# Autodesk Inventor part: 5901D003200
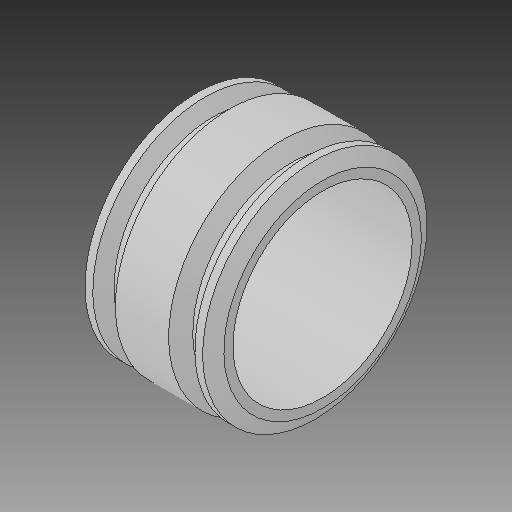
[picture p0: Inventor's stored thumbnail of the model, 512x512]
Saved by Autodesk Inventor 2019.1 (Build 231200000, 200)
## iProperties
Created: 2017-06
Part Number: 5901D003200
Material: Generic
Description: PLASSON COUPLER 20''DIPS
Document SubType Name: Modeling
Designer: KIM
Mass: 96874 g
Surface Area: 34549.7 cm^2
Volume: 96874 cm^3
Density: 1 g/cm^3
Appearance: Default
Author: KIM
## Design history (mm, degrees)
derived "5901D.ipt"
feature "Solid1::5901D.ipt"
tag "TaggingFeature1"
body "Solid1"
other parameters: "d13" = 375.92, "d15" = 187.96, "d16" = 187.96, "d17" = 505.7, "d22" = 632.968, "d23" = 643.382, "d24" = 557.01184, "d25" = 150 deg, "d26" = 150.368, "d27" = 120 deg, "d29" = 316.484, "d35" = 15, "d39" = 0, "d40" = 4, "d41" = 14, "d42" = 0, "d44" = 65.786, "d45" = 505.7, "d47" = 0, "d48" = 303.82464, "d49" = 65.786, "d50" = 60 deg, "d57" = 65.786, "d58" = 65.786, "d62" = 505.7, "d65" = 316.484, "d67" = 30 deg, "d68" = 120 deg, "d69" = 120 deg, "d70" = 120 deg, "d71" = 120 deg, "d72" = 120 deg, "d73" = 643.382, "d76" = 150.368, "d77" = 557.01184, "d_" = 505.7, "L_" = 375.92, "L_1" = 187.96, "D_" = 643.382, "A_" = 316.484, "A_1" = 25.4, "d60" = 187.96
